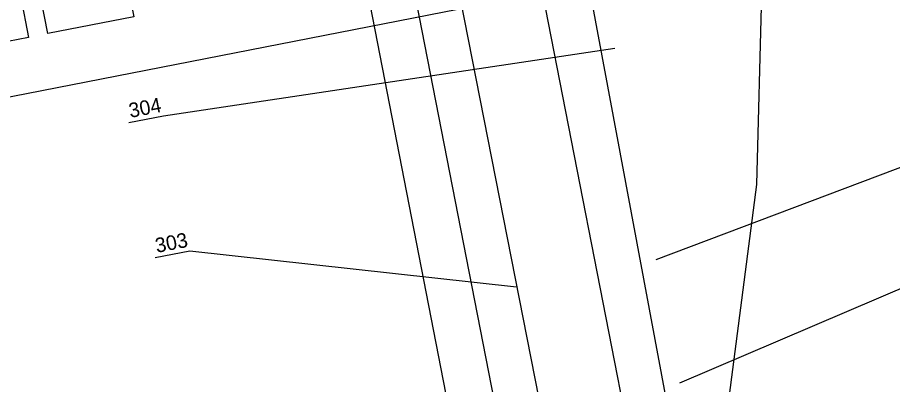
# Model space of a CAD drawing. Extents: x -545967 to -545044, y -1122650 to -1118491.
# Drawn here: x -545748.6 to -545636.3, y -1119398.5 to -1119351.4 of the extents above; entities that cross this region are included whole.
import ezdxf

# ---------------------------------------------------------------- set-up
doc = ezdxf.new("R2010")
doc.units = 0
for name, color, linetype in [('osvětlené plochy-hodnota-obrys', 7, 'Continuous'), ('Rozpiska', 7, 'Continuous'), ('so180602', 7, 'Continuous'), ('Vrstva 10', 7, 'Continuous'), ('Vrstva 63', 7, 'Continuous')]:
    doc.layers.add(name, color=color, linetype=linetype)

msp = doc.modelspace()

# ---------------------------------------------------------------- linework, layer by layer
at = {"layer": 'osvětlené plochy-hodnota-obrys'}
for points in [[(-545700.34, -1119250.43), (-545705.96, -1119221.67), (-545699.04, -1119220.32), (-545660.61, -1119425.92), (-545653.75, -1119372.86), (-545653.1, -1119348.32), (-545657.12, -1119319.99), (-545685.95, -1119192.2), (-545694.33, -1119168.5)], [(-545664.28, -1119515.64), (-545680.45, -1119467.23), (-545736.2, -1119180.74), (-545730.57, -1119179.65)], [(-545730.57, -1119179.65), (-545675.35, -1119462.61), (-545660.82, -1119505.94)], [(-545716.39, -1119223.72), (-545705.99, -1119221.66), (-545669.44, -1119408.76), (-545659.4, -1119462.63), (-545647.69, -1119521.35), (-545640.52, -1119558.73), (-545633.58, -1119589.7), (-545629.52, -1119613.81), (-545623.04, -1119645.06), (-545619.03, -1119667.56), (-545607.52, -1119727.52)], [(-545610.9, -1119760.66), (-545622.84, -1119699.49), (-545637.26, -1119626.87), (-545653.54, -1119543.45), (-545716.39, -1119223.72)]]:
    msp.add_lwpolyline(points, dxfattribs=at)
at = {"layer": 'Rozpiska'}
for p, q in [((-545764.44, -1119265.64), (-545747.15, -1119353.96)), ((-545747.15, -1119353.96), (-545801.07, -1119364.52))]:
    msp.add_line(p, q, dxfattribs=at)
msp.add_lwpolyline([(-545750.95, -1119262.99), (-545733.66, -1119351.32), (-545744.7, -1119353.48), (-545761.99, -1119265.15)], close=True, dxfattribs=at)
at = {"layer": 'Vrstva 10'}
msp.add_line((-545805.3, -1119372.48), (-545513.83, -1119315.44), dxfattribs=at)
at = {"layer": 'Vrstva 63'}
for p, q in [((-545574.48, -1119347.75), (-545666.7, -1119382.49)), ((-545671.98, -1119355.38), (-545729.84, -1119364.07)), ((-545572.23, -1119359.23), (-545663.68, -1119398.34)), ((-545729.84, -1119364.07), (-545734.29, -1119364.93)), ((-545726.45, -1119381.39), (-545730.9, -1119382.26)), ((-545684.59, -1119386.02), (-545726.45, -1119381.39))]:
    msp.add_line(p, q, dxfattribs=at)

# ---------------------------------------------------------------- texts
at = {"layer": 'so180602'}
for s, p in [('304', (-545734.1, -1119364.3)), ('303', (-545730.71, -1119381.62))]:
    msp.add_text(s, height=1.875, rotation=10.9955, dxfattribs=at).set_placement(p)

doc.saveas('drawing.dxf')
